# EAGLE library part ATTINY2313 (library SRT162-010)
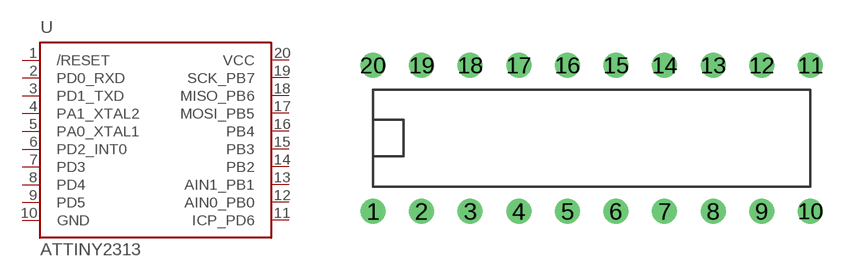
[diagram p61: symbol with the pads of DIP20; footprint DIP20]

Designator prefix U

## ATTINY2313  [DIP20]
1  /RESET
2  PD0_RXD
3  PD1_TXD
4  PA1_XTAL2
5  PA0_XTAL1
6  PD2_INT0
7  PD3
8  PD4
9  PD5
10  GND  pwr
11  ICP_PD6  pas
12  AIN0_PB0  pas
13  AIN1_PB1  pas
14  PB2  pas
15  PB3  pas
16  PB4  pas
17  MOSI_PB5  pas
18  MISO_PB6  pas
19  SCK_PB7  pas
20  VCC  pwr

## Footprint DIP20 (pad centres in mm)
drill 0.8 round: 1 -11.43,-3.81; 2 -8.89,-3.81; 3 -6.35,-3.81; 4 -3.81,-3.81; 5 -1.27,-3.81; 6 1.27,-3.81; 7 3.81,-3.81; 8 6.35,-3.81; 9 8.89,-3.81; 10 11.43,-3.81; 11 11.43,3.81; 12 8.89,3.81; 13 6.35,3.81; 14 3.81,3.81; 15 1.27,3.81; 16 -1.27,3.81; 17 -3.81,3.81; 18 -6.35,3.81; 19 -8.89,3.81; 20 -11.43,3.81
